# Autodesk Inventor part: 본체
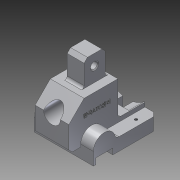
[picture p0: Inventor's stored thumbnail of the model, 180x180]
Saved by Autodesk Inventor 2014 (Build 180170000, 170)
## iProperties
Created: 2016-11
Part Number: 본체
Material: Aluminum 6061
Document SubType Name: Modeling
Designer: user
Density: 2.71 g/cm^3
Appearance: Aluminum - Flat
Mass: 462.906 g
Surface Area: 317.29 cm^2
Volume: 170.814 cm^3
Author: user
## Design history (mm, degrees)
sketch "Sketch1"
  geometry: L1 (0, 0)-(0, 15); L2 (26, 15)-(76, 15); L3 (76, 15)-(76, 0); L4 (76, 0)-(0, 0); A1 r 13 centre (13, 15) between (26, 15) and (0, 15)
  constraints: 8 end point, 2 parallel, 2 point on circle, 1 centre point, 1 horizontal alignment, 1 perpendicular, 1 point on line, 1 vertical
  dimensions: "d1" = 15 distance of L1.start L1.end; "d2" = 76 distance of L3.end L1.start; "d3" = 26 diameter of A1
extrude "Extrusion1" new body sketch "Sketch1" distance "d4" = 70; taper "d5" = 0 deg
sketch "Sketch2"
  geometry: L1 (0, 0)-(-15, 0) reference; L2 (0, 76)-(0, 0) reference; L3 (-15, 26)-(-15, 76) reference; L4 (0, 3)-(-7, 3); L5 (-7, 3)-(-7, 23); L6 (-7, 23)-(0, 23)
  constraints: 6 end point, 3 perpendicular, 2 point on line
  dimensions: "d6" = 7 distance of L5.end L6.end; "d7" = 20 distance of L4.end L5.end; "d8" = 3 distance between parallel lines of L1 L4
extrude "Extrusion2" cut sketch "Sketch2" distance "d9" = 70; taper "d10" = 0 deg
workplane "Work Plane1"
sketch "Sketch3"
  geometry: L1 (23, 0)-(23, 7) reference; L2 (23, 7)-(3, 7) reference; L3 (3, 7)-(3, 0) reference; L4 (3, 0)-(0, 0) reference; L5 (0, 0)-(0, 15) reference; L6 (26, 15)-(76, 15) reference; L7 (76, 15)-(76, 0) reference; L8 (76, 0)-(23, 0) reference; L9 (76, 15)-(76, 20); L10 (76, 20)-(44, 20); L11 (44, 20)-(44, 15); A1 r 13 centre (13, 15) between (26, 15) and (0, 15) reference; 1 further point
  constraints: 6 end point, 3 perpendicular, 1 point on line
  dimensions: "d12" = 32 distance of L9.end L10.end; "d13" = 5 distance of L10.end L11.end
extrude "Extrusion3" join sketch "Sketch3" distance "d14" = 40; taper "d15" = 0 deg
sketch "Sketch4"
  geometry: L1 (23, 0)-(23, 7) reference; L2 (23, 7)-(3, 7) reference; L3 (3, 7)-(3, 0) reference; L4 (3, 0)-(0, 0) reference; L5 (0, 0)-(0, 15) reference; L6 (26, 15)-(76, 15) reference; L7 (76, 15)-(76, 0) reference; L8 (76, 0)-(23, 0) reference; L9 (76, 20)-(76, 15) reference; L10 (44, 15)-(76, 15) reference; L11 (44, 15)-(44, 20) reference; L12 (44, 20)-(76, 20) reference; L13 (44, 20)-(44, 60); L14 (44, 60)-(4, 60); L15 (4, 60)-(-14, 42); L16 (-14, 42)-(-14, 12); L17 (-14, 12)-(0, 12); L18 (44, 20)-(44, 15); L19 (44, 15)-(26, 15); L20 (0, 15)-(0, 12); A1 r 13 centre (13, 15) between (26, 15) and (0, 15) reference; A2 r 13 centre (13, 15) between (26, 15) and (0, 15); 1 further point
  constraints: 16 end point, 5 perpendicular, 2 parallel, 2 point on circle, 2 point on line, 2 tangent, 1 centre point, 1 coincident, 1 collinear
  dimensions: "d18" = 45 deg angle of L15 L14; "d21" = 48 distance between parallel lines of L17 L14; "d22" = 60 distance between parallel lines of L8 L14; "d23" = 30 distance of L15.end L16.end; "d24" = 40 distance of L13.end L14.end
extrude "Extrusion4" join sketch "Sketch4" distance "d25" = 40; taper "d26" = 0 deg
workplane "Work Plane2"
sketch "Sketch5"
  geometry: L1 (44, 60)-(4, 60) reference; L2 (39, 60)-(39, 90); L3 (39, 90)-(14, 90); L4 (14, 90)-(14, 60); L5 (39, 60)-(14, 60); L6 (76, 0)-(23, 0) reference; L7 (44, 60)-(44, 20) reference; 1 further point
  constraints: 8 end point, 3 perpendicular, 2 point on line, 1 collinear
  dimensions: "d28" = 90 distance between parallel lines of L6 L3; "d29" = 25 distance of L2.end L3.end; "d30" = 5 distance between parallel lines of L7 L2
extrude "Extrusion5" join sketch "Sketch5" stored distance "d31" = 20; taper "d32" = 0 deg
sketch "Sketch6"
  geometry: L1 (0, 15)-(-70, 15) reference; C1 r 29 at (-35, -27); 1 further point
  constraints: 1 centre point, 1 midpoint, 1 vertical alignment
  dimensions: "d33" = 58 diameter of C1; "d34" = 42 distance from line of L1 C1.centre
extrude "Extrusion6" cut sketch "Sketch6" distance "d35" = 18; taper "d36" = 0 deg
sketch "Sketch7"
  geometry: L1 (0, 15)-(-70, 15) reference; L2 (-53.894, -5)-(-55, -5) reference; L3 (-29, 15)-(-29, 1.373); L4 (-41, 15)-(-41, 1.373); L5 (-41, 15)-(-29, 15); A1 r 29 centre (-35, -27) between (-16.106, -5) and (-53.894, -5) reference; 2 further points
  constraints: 6 end point, 2 midpoint, 2 point on circle, 2 point on line, 2 vertical alignment, 1 parallel, 1 perpendicular
  dimensions: "d37" = 12 distance between parallel lines of L4 L3
extrude "Extrusion7" cut sketch "Sketch7" distance "d38" = 18; taper "d39" = 0 deg
sketch "Sketch8"
  geometry: L1 (0, 0)-(0, 50) reference; L2 (0, 50)-(-15, 50) reference; L3 (-55, 50)-(-70, 50) reference; 3 further points
  dimensions: "d40" = 18 distance from line of L2 point (-7.5, 32); "d41" = 18 distance from line of L3 point (-62.5, 32); "d42" = 55 distance of point (-7.5, 32) point (-62.5, 32); "d43" = 7.5 distance from line of L1 point (-7.5, 32)
hole "Hole1" sketch "Sketch8" at (-7.5, 32), (-62.5, 32) diameter "d44" = 3.242; stored, may be unused: countersink angle "d48" = 90 deg, drill point angle "d50" = 118 deg; dims "d45" = 15, "d46" = 4, "d47" = 2, "d49" = 8
sketch "Sketch9"
  geometry: L1 (-26, 60)-(-14, 60) reference; C1 r 14.5 at (-20, 18); 2 further points
  constraints: 1 centre point, 1 midpoint, 1 vertical alignment
  dimensions: "d51" = 29 diameter of C1; "d52" = 42 distance from line of L1 C1.centre
extrude "Extrusion8" cut sketch "Sketch9" distance "d53" = 7; taper "d54" = 0 deg
sketch "Sketch10"
  geometry: C1 r 14.5 at (0, 0) reference; C2 r 10 at (0, 0); 1 further point
  constraints: 1 centre point, 1 coincident
  dimensions: "d55" = 20 diameter of C2
extrude "Extrusion9" cut sketch "Sketch10" stored distance "d56" = 7; taper "d57" = 0 deg
sketch "Sketch11"
  geometry: L1 (-60, 39)-(-90, 39) reference; L2 (0, 76)-(0, 23) reference; C1 r 4 at (-77, 26.5); 1 further point
  constraints: 1 centre point
  dimensions: "d58" = 8 diameter of C1; "d59" = 12.5 distance from line of L1 C1.centre; "d60" = 77 distance from line of L2 C1.centre
extrude "Extrusion10" cut sketch "Sketch11" stored distance "d61" = 7; taper "d62" = 0 deg
chamfer "Chamfer1" distance "d63" = 4; stored, may be unused: second distance "d64" = 2, angle "d65" = 45 deg
chamfer "Chamfer2" distance "d66" = 1; stored, may be unused: second distance "d67" = 2, angle "d68" = 45 deg
chamfer "Chamfer3" distance "d69" = 5; stored, may be unused: second distance "d70" = 2, angle "d71" = 45 deg
fillet "Fillet1" dims "d72" = 5
fillet "Fillet2" dims "d73" = 3
workplane "Work Plane3"
sketch "Sketch12"
  geometry: L1 (-23, 44)-(-60, 44) reference; L2 (-60, 44)-(-60, 4) reference; 2 further points
  constraints: 1 other
  dimensions: "d75" = 25 distance from line of L1 point (-42, 19); "d76" = 18 distance from line of L2 point (-42, 19)
emboss "Emboss1" sketch "Sketch12" dims "d1" = 15, "d2" = 76, "d3" = 26, "d77" = 0.5, "d78" = 0
body "Solid1"
node "Projected Loop1"
node "Projected Loop2"
node "Projected Loop3"
other parameters: "d11" = -15, "d27" = -35, "d74" = 78.75
